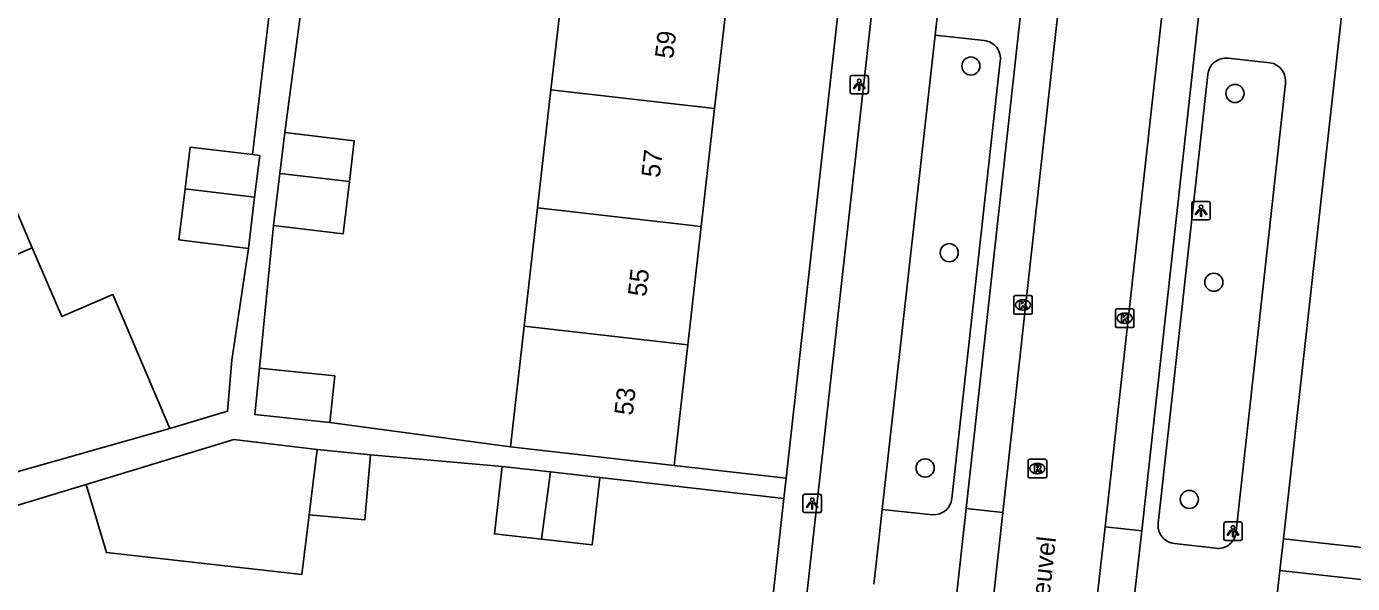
# Model space of a CAD drawing. Extents: x 162026 to 163499, y 387297 to 388169.
# Drawn here: x 162240.9 to 162312.4, y 387863.1 to 387893.2 of the extents above; entities that cross this region are included whole.
import ezdxf

# ---------------------------------------------------------------- set-up
doc = ezdxf.new("R2010")
doc.units = 0
for name, color, linetype in [('IMGEO_Boom', 7, 'Continuous'), ('IMGEO_Fietspad_gesloten', 7, 'Continuous'), ('IMGEO_Kolk', 7, 'Continuous'), ('IMGEO_Lichtpunt', 7, 'Continuous'), ('IMGEO_Openbare_ruimte_label', 7, 'Continuous'), ('IMGEO_Pand', 7, 'Continuous'), ('IMGEO_Pand_nummerreeks', 7, 'Continuous'), ('IMGEO_Rijbaan_lokaal_gesloten', 7, 'Continuous'), ('IMGEO_Rioolput', 7, 'Continuous'), ('IMGEO_Voetpad_open', 7, 'Continuous')]:
    doc.layers.add(name, color=color, linetype=linetype)

msp = doc.modelspace()

# ---------------------------------------------------------------- linework, layer by layer
at = {"layer": 'IMGEO_Boom'}
for centre in [(162291.821, 387891.022), (162306.06, 387889.541), (162290.652, 387880.948), (162304.922, 387879.357), (162289.354, 387869.333), (162303.597, 387867.637)]:
    msp.add_circle(centre, 0.489, dxfattribs=at)
at = {"layer": 'IMGEO_Fietspad_gesloten'}
for points in [[(162296.034, 387979.848), (162290.464, 387929.711), (162288.097, 387908.488), (162278.956, 387826.545), (162278.87, 387825.665), (162278.372, 387825.72), (162277.589, 387818.699), (162278.067, 387818.669), (162270.183, 387748.502), (162261.381, 387669.505), (162260.87, 387664.615)], [(162289.894, 387892.691), (162290.021, 387893.825), (162290.158, 387895.051)], [(162287.035, 387867.097), (162289.894, 387892.691)], [(162286.582, 387863.057), (162286.832, 387865.282), (162287.035, 387867.097)]]:
    msp.add_lwpolyline(points, dxfattribs=at)
at = {"layer": 'IMGEO_Kolk'}
for p, q in [((162294.128, 387877.706), (162294.128, 387878.558)), ((162294.203, 387878.632), (162295.055, 387878.632)), ((162295.129, 387878.558), (162295.129, 387877.706)), ((162294.639, 387877.852), (162294.614, 387877.852)), ((162294.616, 387878.412), (162294.641, 387878.412)), ((162299.614, 387876.986), (162299.614, 387877.838)), ((162299.689, 387877.912), (162300.541, 387877.912)), ((162300.615, 387877.838), (162300.615, 387876.986)), ((162295.055, 387877.632), (162294.203, 387877.632)), ((162300.125, 387877.132), (162300.1, 387877.132)), ((162300.102, 387877.692), (162300.127, 387877.692)), ((162300.541, 387876.912), (162299.689, 387876.912))]:
    msp.add_line(p, q, dxfattribs=at)
for points in [[(162294.128, 387877.706), (162294.128, 387878.558)], [(162294.203, 387878.632), (162295.055, 387878.632)], [(162295.129, 387878.558), (162295.129, 387877.706)], [(162294.449, 387878.332), (162294.572, 387878.332), (162294.572, 387878.181), (162294.702, 387878.332), (162294.866, 387878.332), (162294.72, 387878.181), (162294.873, 387877.932), (162294.721, 387877.932), (162294.636, 387878.096), (162294.572, 387878.029), (162294.572, 387877.932), (162294.449, 387877.932), (162294.449, 387878.332)], [(162299.614, 387876.986), (162299.614, 387877.838)], [(162299.689, 387877.912), (162300.541, 387877.912)], [(162300.615, 387877.838), (162300.615, 387876.986)], [(162295.055, 387877.632), (162294.203, 387877.632)], [(162299.935, 387877.612), (162300.058, 387877.612), (162300.058, 387877.461), (162300.188, 387877.612), (162300.352, 387877.612), (162300.206, 387877.461), (162300.359, 387877.212), (162300.207, 387877.212), (162300.122, 387877.376), (162300.058, 387877.309), (162300.058, 387877.212), (162299.935, 387877.212), (162299.935, 387877.612)], [(162300.541, 387876.912), (162299.689, 387876.912)]]:
    msp.add_lwpolyline(points, dxfattribs=at)
for centre, start, end in [((162294.205, 387878.556), 91.55205, 178.44795), ((162294.205, 387878.556), 91.55205, 178.44795), ((162295.053, 387878.556), 1.55205, 88.44795), ((162295.053, 387878.556), 1.55205, 88.44795), ((162299.691, 387877.836), 91.55205, 178.44795), ((162299.691, 387877.836), 91.55205, 178.44795), ((162300.539, 387877.836), 1.55205, 88.44795), ((162300.539, 387877.836), 1.55205, 88.44795), ((162294.205, 387877.708), 181.55205, 268.44795), ((162294.205, 387877.708), 181.55205, 268.44795), ((162295.053, 387877.708), 271.55205, 358.44795), ((162295.053, 387877.708), 271.55205, 358.44795), ((162299.691, 387876.988), 181.55205, 268.44795), ((162299.691, 387876.988), 181.55205, 268.44795), ((162300.539, 387876.988), 271.55205, 358.44795), ((162300.539, 387876.988), 271.55205, 358.44795)]:
    msp.add_arc(centre, 0.0765, start, end, dxfattribs=at)
for centre, major_axis, ratio, start_param, end_param in [((162294.615, 387878.132), (-0.387, 0.002), 0.722429, 4.712389, 7.853982), ((162294.64, 387878.132), (-0.39, 0.002), 0.717154, 1.570796, 4.712389), ((162300.101, 387877.412), (-0.387, 0.002), 0.722429, 4.712389, 7.853982), ((162300.126, 387877.412), (-0.39, 0.002), 0.717154, 1.570796, 4.712389)]:
    msp.add_ellipse(centre, major_axis=major_axis, ratio=ratio, start_param=start_param, end_param=end_param, dxfattribs=at)
at = {"layer": 'IMGEO_Lichtpunt'}
for p, q in [((162285.302, 387890.423), (162285.302, 387889.616)), ((162285.302, 387890.423), (162285.302, 387889.616)), ((162286.204, 387890.518), (162285.396, 387890.518)), ((162286.204, 387890.518), (162285.396, 387890.518)), ((162286.298, 387889.616), (162286.298, 387890.423)), ((162286.298, 387889.616), (162286.298, 387890.423)), ((162285.396, 387889.522), (162286.204, 387889.522)), ((162285.396, 387889.522), (162286.204, 387889.522)), ((162303.734, 387883.623), (162303.734, 387882.816)), ((162303.734, 387883.623), (162303.734, 387882.816)), ((162304.636, 387883.718), (162303.828, 387883.718)), ((162304.636, 387883.718), (162303.828, 387883.718)), ((162304.73, 387882.816), (162304.73, 387883.623)), ((162304.73, 387882.816), (162304.73, 387883.623)), ((162303.828, 387882.722), (162304.636, 387882.722)), ((162303.828, 387882.722), (162304.636, 387882.722)), ((162282.762, 387867.824), (162282.762, 387867.017)), ((162282.762, 387867.824), (162282.762, 387867.017)), ((162283.664, 387867.919), (162282.856, 387867.919)), ((162283.664, 387867.919), (162282.856, 387867.919)), ((162283.758, 387867.017), (162283.758, 387867.824)), ((162283.758, 387867.017), (162283.758, 387867.824)), ((162282.856, 387866.923), (162283.664, 387866.923)), ((162282.856, 387866.923), (162283.664, 387866.923)), ((162305.457, 387866.325), (162305.457, 387865.518)), ((162305.457, 387866.325), (162305.457, 387865.518)), ((162306.359, 387866.42), (162305.551, 387866.42)), ((162306.359, 387866.42), (162305.551, 387866.42)), ((162306.453, 387865.518), (162306.453, 387866.325)), ((162306.453, 387865.518), (162306.453, 387866.325)), ((162305.551, 387865.424), (162306.359, 387865.424)), ((162305.551, 387865.424), (162306.359, 387865.424))]:
    msp.add_line(p, q, dxfattribs=at)
for points in [[(162285.676, 387890.087), (162285.715, 387890.059), (162285.527, 387889.797), (162285.489, 387889.824), (162285.676, 387890.087)], [(162285.778, 387890.039), (162285.825, 387890.039), (162285.825, 387889.717), (162285.778, 387889.717), (162285.778, 387890.039)], [(162285.888, 387890.059), (162285.926, 387890.086), (162286.113, 387889.824), (162286.074, 387889.796), (162285.888, 387890.059)], [(162304.108, 387883.287), (162304.147, 387883.259), (162303.959, 387882.997), (162303.921, 387883.024), (162304.108, 387883.287)], [(162304.21, 387883.239), (162304.257, 387883.239), (162304.257, 387882.917), (162304.21, 387882.917), (162304.21, 387883.239)], [(162304.32, 387883.259), (162304.358, 387883.286), (162304.545, 387883.024), (162304.506, 387882.996), (162304.32, 387883.259)], [(162283.136, 387867.488), (162283.175, 387867.46), (162282.987, 387867.198), (162282.949, 387867.225), (162283.136, 387867.488)], [(162283.238, 387867.44), (162283.285, 387867.44), (162283.285, 387867.118), (162283.238, 387867.118), (162283.238, 387867.44)], [(162283.348, 387867.46), (162283.386, 387867.487), (162283.573, 387867.225), (162283.534, 387867.197), (162283.348, 387867.46)], [(162305.831, 387865.989), (162305.87, 387865.961), (162305.682, 387865.699), (162305.644, 387865.726), (162305.831, 387865.989)], [(162305.933, 387865.941), (162305.98, 387865.941), (162305.98, 387865.619), (162305.933, 387865.619), (162305.933, 387865.941)], [(162306.043, 387865.961), (162306.081, 387865.988), (162306.268, 387865.726), (162306.229, 387865.698), (162306.043, 387865.961)]]:
    msp.add_lwpolyline(points, dxfattribs=at)
for centre in [(162285.801, 387890.221), (162304.233, 387883.421), (162283.261, 387867.622), (162305.956, 387866.123)]:
    msp.add_circle(centre, 0.0994, dxfattribs=at)
for centre, start, end in [((162285.396, 387890.423), 90, 180), ((162285.396, 387890.423), 90, 180), ((162286.204, 387890.423), 0, 90), ((162286.204, 387890.423), 0, 90), ((162285.396, 387889.616), 180, 270), ((162285.396, 387889.616), 180, 270), ((162286.204, 387889.616), 270, 0), ((162286.204, 387889.616), 270, 360), ((162303.828, 387883.623), 90, 180), ((162303.828, 387883.623), 90, 180), ((162304.636, 387883.623), 0, 90), ((162304.636, 387883.623), 0, 90), ((162303.828, 387882.816), 180, 270), ((162303.828, 387882.816), 180, 270), ((162304.636, 387882.816), 270, 0), ((162304.636, 387882.816), 270, 360), ((162282.856, 387867.824), 90, 180), ((162282.856, 387867.824), 90, 180), ((162283.664, 387867.824), 0, 90), ((162283.664, 387867.824), 0, 90), ((162282.856, 387867.017), 180, 270), ((162282.856, 387867.017), 180, 270), ((162283.664, 387867.017), 270, 0), ((162283.664, 387867.017), 270, 360), ((162305.551, 387866.325), 90, 180), ((162305.551, 387866.325), 90, 180), ((162306.359, 387866.325), 0, 90), ((162306.359, 387866.325), 0, 90), ((162305.551, 387865.518), 180, 270), ((162305.551, 387865.518), 180, 270), ((162306.359, 387865.518), 270, 0), ((162306.359, 387865.518), 270, 360)]:
    msp.add_arc(centre, 0.0946, start, end, dxfattribs=at)
at = {"layer": 'IMGEO_Pand'}
for points in [[(162269.174, 387889.737), (162269.898, 387896.106)], [(162278.725, 387895.102), (162278.001, 387888.733)], [(162269.174, 387889.737), (162268.45, 387883.367)], [(162278.001, 387888.733), (162269.174, 387889.737)], [(162278.001, 387888.733), (162277.277, 387882.364)], [(162254.553, 387885.217), (162254.82, 387887.429)], [(162258.304, 387884.8), (162258.567, 387886.977), (162254.82, 387887.429)], [(162238.698, 387887.042), (162241.202, 387881.22)], [(162249.447, 387884.397), (162249.719, 387886.651), (162253.073, 387886.246)], [(162253.073, 387886.246), (162253.466, 387886.199), (162253.194, 387883.95)], [(162254.215, 387882.415), (162254.553, 387885.217)], [(162254.553, 387885.217), (162258.304, 387884.8)], [(162252.861, 387881.185), (162249.114, 387881.637), (162249.447, 387884.397)], [(162253.194, 387883.95), (162249.447, 387884.397)], [(162258.304, 387884.8), (162257.962, 387881.963), (162254.215, 387882.415)], [(162253.194, 387883.95), (162252.861, 387881.185)], [(162268.45, 387883.367), (162267.725, 387876.989)], [(162268.45, 387883.367), (162277.277, 387882.364)], [(162277.277, 387882.364), (162276.552, 387875.985)], [(162241.202, 387881.22), (162233.081, 387877.727)], [(162241.202, 387881.22), (162242.796, 387877.513), (162245.543, 387878.694), (162248.629, 387871.455)], [(162267.725, 387876.989), (162266.984, 387870.468)], [(162276.552, 387875.985), (162267.725, 387876.989)], [(162276.552, 387875.985), (162275.811, 387869.465)], [(162257.253, 387871.794), (162253.199, 387872.213), (162253.459, 387874.721)], [(162253.459, 387874.721), (162257.512, 387874.301), (162257.253, 387871.794)], [(162248.629, 387871.455), (162240.067, 387869.028)], [(162244.103, 387868.45), (162252.068, 387870.87), (162256.567, 387870.335)], [(162256.133, 387866.798), (162256.567, 387870.335)], [(162259.444, 387870.039), (162259.141, 387866.538), (162256.133, 387866.798)], [(162256.567, 387870.335), (162259.444, 387870.039)], [(162275.811, 387869.465), (162266.984, 387870.468)], [(162268.67, 387865.488), (162266.123, 387865.777), (162266.535, 387869.416)], [(162266.535, 387869.416), (162269.155, 387869.119)], [(162269.155, 387869.119), (162268.67, 387865.488)], [(162271.802, 387868.819), (162271.39, 387865.18), (162268.67, 387865.488)], [(162269.155, 387869.119), (162271.802, 387868.819)], [(162256.133, 387866.798), (162255.74, 387863.589), (162245.204, 387864.77), (162244.103, 387868.45)]]:
    msp.add_lwpolyline(points, dxfattribs=at)
at = {"layer": 'IMGEO_Rijbaan_lokaal_gesloten'}
for points in [[(162304.811, 387968.292), (162296.246, 387891.427), (162293.541, 387866.933)], [(162308.539, 387951.558), (162302.841, 387900.241), (162299.054, 387866.158)], [(162293.019, 387862.21), (162293.541, 387866.933)], [(162299.054, 387866.158), (162298.53, 387861.44)]]:
    msp.add_lwpolyline(points, dxfattribs=at)
at = {"layer": 'IMGEO_Rioolput'}
for p, q in [((162294.906, 387868.877), (162294.906, 387869.729)), ((162294.981, 387869.803), (162295.833, 387869.803)), ((162295.394, 387869.583), (162295.419, 387869.583)), ((162295.907, 387869.729), (162295.907, 387868.877)), ((162295.833, 387868.803), (162294.981, 387868.803)), ((162295.417, 387869.023), (162295.392, 387869.023))]:
    msp.add_line(p, q, dxfattribs=at)
for points in [[(162294.906, 387868.877), (162294.906, 387869.729)], [(162294.981, 387869.803), (162295.833, 387869.803)], [(162295.495, 387869.501), (162295.243, 387869.503), (162295.243, 387869.103)], [(162295.243, 387869.103), (162295.367, 387869.103), (162295.367, 387869.265), (162295.378, 387869.265)], [(162295.421, 387869.422), (162295.367, 387869.422), (162295.367, 387869.341)], [(162295.367, 387869.341), (162295.419, 387869.341)], [(162295.425, 387869.236), (162295.496, 387869.103), (162295.636, 387869.103), (162295.571, 387869.229)], [(162295.907, 387869.729), (162295.907, 387868.877)], [(162295.833, 387868.803), (162294.981, 387868.803)]]:
    msp.add_lwpolyline(points, dxfattribs=at)
for centre, radius, start, end in [((162294.983, 387869.727), 0.0765, 91.55205, 178.44795), ((162294.983, 387869.727), 0.0765, 91.55205, 178.44795), ((162295.377, 387869.212), 0.0533, 26.02933, 88.69889), ((162295.403, 387869.53), 0.19, 274.7715, 282.96867), ((162295.427, 387869.326), 0.0964, 77.00612, 93.18647), ((162295.441, 387869.383), 0.0378, 276.66336, 79.67722), ((162295.494, 387869.391), 0.109, 350.36119, 89.41601), ((162295.492, 387869.391), 0.112, 277.58423, 350.98172), ((162295.476, 387869.176), 0.108, 29.51342, 73.79051), ((162295.831, 387869.727), 0.0765, 1.55205, 88.44795), ((162295.831, 387869.727), 0.0765, 1.55205, 88.44795), ((162294.983, 387868.879), 0.0765, 181.55205, 268.44795), ((162294.983, 387868.879), 0.0765, 181.55205, 268.44795), ((162295.831, 387868.879), 0.0765, 271.55205, 358.44795), ((162295.831, 387868.879), 0.0765, 271.55205, 358.44795)]:
    msp.add_arc(centre, radius, start, end, dxfattribs=at)
for centre, major_axis, ratio, start_param, end_param in [((162295.393, 387869.303), (-0.387, 0.002), 0.722429, 4.712389, 7.853982), ((162295.418, 387869.303), (-0.39, 0.002), 0.717154, 1.570796, 4.712389)]:
    msp.add_ellipse(centre, major_axis=major_axis, ratio=ratio, start_param=start_param, end_param=end_param, dxfattribs=at)
at = {"layer": 'IMGEO_Voetpad_open'}
for points in [[(162291.572, 387867.15), (162294.303, 387892.007), (162302.723, 387967.594)], [(162291.153, 387952.205), (162285.089, 387897.861), (162281.859, 387868.778)], [(162301.044, 387865.937), (162304.798, 387900.046), (162310.512, 387951.338)], [(162317.966, 387949.406), (162317.334, 387943.671), (162308.672, 387865.517)], [(162254.82, 387887.429), (162255.858, 387895.34)], [(162253.073, 387886.246), (162253.985, 387893.807)], [(162292.541, 387892.392), (162289.894, 387892.691)], [(162307.939, 387891.2), (162305.694, 387891.445)], [(162290.801, 387867.696), (162293.398, 387891.278)], [(162304.597, 387890.56), (162301.919, 387866.359)], [(162306.134, 387865.916), (162308.786, 387890.082)], [(162253.459, 387874.721), (162254.215, 387882.415)], [(162248.629, 387871.455), (162251.735, 387872.392), (162251.972, 387875.159), (162252.861, 387881.185)], [(162266.984, 387870.468), (162257.253, 387871.794)], [(162259.444, 387870.039), (162266.535, 387869.416)], [(162281.859, 387868.778), (162275.811, 387869.465)], [(162271.802, 387868.819), (162281.738, 387867.693)], [(162281.859, 387868.778), (162281.738, 387867.693)], [(162232.282, 387864.869), (162244.103, 387868.45)], [(162281.738, 387867.693), (162278.721, 387840.526)], [(162287.035, 387867.097), (162289.772, 387866.807)], [(162291.036, 387862.429), (162291.572, 387867.15)], [(162293.541, 387866.933), (162291.572, 387867.15)], [(162299.054, 387866.158), (162301.044, 387865.937)], [(162300.507, 387861.221), (162301.044, 387865.937)], [(162302.804, 387865.257), (162305.009, 387865.005)], [(162308.672, 387865.517), (162308.483, 387863.811)], [(162308.672, 387865.517), (162314.843, 387864.833)], [(162305.479, 387838.176), (162307.809, 387859.089), (162307.958, 387859.072), (162308.483, 387863.811)], [(162308.483, 387863.811), (162314.493, 387863.145)]]:
    msp.add_lwpolyline(points, dxfattribs=at)
for centre, radius, start, end in [((162292.448, 387891.434), 0.962, 350.67144, 84.47072), ((162305.577, 387890.467), 0.985, 83.18512, 174.60429), ((162307.794, 387890.21), 1, 352.62663, 81.66871), ((162289.812, 387867.8), 0.994, 267.67803, 353.97243), ((162302.893, 387866.235), 0.982, 172.73118, 264.80369), ((162305.149, 387865.982), 0.987, 261.82957, 356.16999)]:
    msp.add_arc(centre, radius, start, end, dxfattribs=at)

# ---------------------------------------------------------------- texts
at = {"layer": 'IMGEO_Openbare_ruimte_label'}
msp.add_text('De Stoutheuvel', height=1, rotation=83.68512, dxfattribs=at).set_placement((162295.41, 387856.488))
at = {"layer": 'IMGEO_Pand_nummerreeks'}
for s, p in [('59', (162275.766, 387891.381)), ('57', (162275.037, 387884.966)), ('55', (162274.308, 387878.551)), ('53', (162273.579, 387872.136))]:
    msp.add_text(s, height=1, rotation=83.51597, dxfattribs=at).set_placement(p)

doc.saveas('drawing.dxf')
